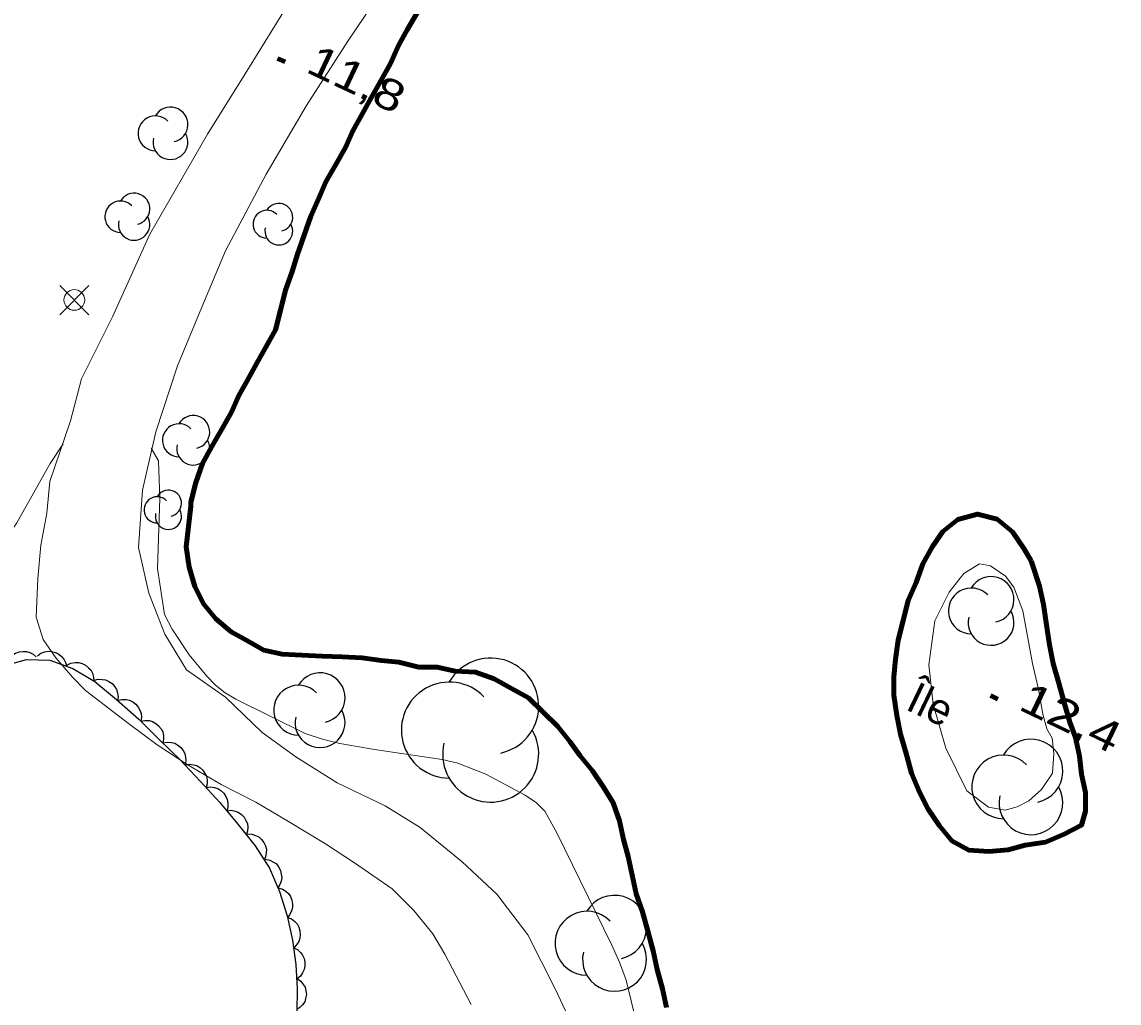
# Model space of a CAD drawing. Extents: x 355726 to 357533, y 5103782 to 5105258.
# Drawn here: x 356176.5 to 356229.5, y 5105042.4 to 5105089.8 of the extents above; entities that cross this region are included whole.
import ezdxf

# ---------------------------------------------------------------- set-up
doc = ezdxf.new("R2010")
doc.units = 0
doc.header["$LTSCALE"] = 0.6
for name, pattern in [('DASH_DOUBLE_DOT', [9.2, 5, -1.2, 0.3, -1.2, 0.3, -1.2]), ('DOT_DASHED', [7.7, 5, -1.2, 0.3, -1.2]), ('LONG_DASHED', [7.5, 6, -1.5])]:
    doc.linetypes.add(name, pattern=pattern)
for name, color, linetype, lineweight in [('19', 7, 'Continuous', 13), ('2', 7, 'LONG_DASHED', 13), ('3', 7, 'Continuous', 140), ('36', 7, 'Continuous', 13), ('4', 7, 'DASH_DOUBLE_DOT', 53), ('44', 7, 'Continuous', 25)]:
    doc.layers.add(name, color=color, linetype=linetype, lineweight=lineweight)
doc.layers.add('8', color=7, linetype='Continuous')

msp = doc.modelspace()

# ---------------------------------------------------------------- linework, layer by layer
at = {"layer": '19'}
for points in [[(356203.49, 5105040.41), (356202.22, 5105043.09), (356200.9, 5105045.7), (356199.41, 5105047.66), (356197.73, 5105049.22), (356195.7, 5105050.88), (356194.01, 5105051.93), (356191.69, 5105053.04), (356189.7, 5105054.3), (356188.06, 5105055.48), (356186.29, 5105057.18), (356184.41, 5105058.51), (356183.36, 5105060.24), (356182.59, 5105062.21), (356182.09, 5105064.43), (356182.28, 5105067.2), (356182.93, 5105070.01), (356183.98, 5105073.2), (356185.15, 5105076.04), (356186.3, 5105078.76), (356188.26, 5105082.47), (356190.2, 5105085.8), (356192.2, 5105088.9), (356194.22, 5105091.91)], [(356198.16, 5105042.32), (356196.89, 5105044.76), (356196.32, 5105045.74), (356195.39, 5105046.87), (356194.35, 5105047.92), (356192.53, 5105049.17), (356191.13, 5105050.09), (356189.34, 5105051.18), (356187.76, 5105052.11), (356186.09, 5105052.97), (356184.44, 5105053.93), (356182.99, 5105054.88), (356181.61, 5105055.91), (356179.53, 5105057.51), (356178.9, 5105058.16), (356178.09, 5105059.09), (356177.48, 5105059.98), (356177.14, 5105061.05), (356177.23, 5105062.93), (356177.37, 5105064.54), (356177.65, 5105066.08), (356177.81, 5105067.62), (356178.8, 5105070.54), (356179.33, 5105072.58), (356180.83, 5105075.57), (356182.63, 5105079.57), (356185.43, 5105084.4), (356187.25, 5105087.33), (356189.51, 5105091.01)]]:
    msp.add_lwpolyline(points, dxfattribs=at)
at = {"layer": '2', "linetype": 'Continuous'}
for points in [[(356167.83, 5105042.71), (356170, 5105049.92), (356170.19, 5105050.84), (356170.7, 5105052.83), (356172.2, 5105057.91), (356172.44, 5105058.83), (356172.7, 5105060.15), (356173.33, 5105061.38), (356174.21, 5105062.77), (356176.21, 5105065.62), (356177.82, 5105068.49), (356178.45, 5105069.43)], [(356182.7, 5105069.22), (356183.06, 5105068.62), (356183.12, 5105066.8), (356183, 5105063.4), (356183.35, 5105061.18), (356183.72, 5105060.48), (356184.53, 5105059.24), (356185.39, 5105058.2), (356185.81, 5105057.76), (356186.27, 5105057.4), (356186.79, 5105057.09), (356190.15, 5105055.43), (356190.98, 5105055.15), (356191.82, 5105054.95), (356193.49, 5105054.65), (356196.77, 5105054.17), (356197.52, 5105053.99), (356198.88, 5105053.47), (356200.77, 5105052.45), (356201.32, 5105052.08), (356201.72, 5105051.67), (356202.3, 5105050.62), (356204.95, 5105045.23), (356205.33, 5105044.38), (356205.65, 5105043.51), (356206.38, 5105040.51)]]:
    msp.add_lwpolyline(points, dxfattribs=at)
at = {"layer": '2'}
msp.add_lwpolyline([(356225.58, 5105057.57), (356225.29, 5105058.82), (356224.83, 5105061.36), (356224.39, 5105062.51), (356223.99, 5105063.03), (356223.27, 5105063.53), (356222.74, 5105063.63), (356221.98, 5105063.17), (356221.27, 5105062.27), (356220.58, 5105060.87), (356220.29, 5105058.75), (356220.5, 5105056.84), (356221.1, 5105054.72), (356222.12, 5105052.66), (356223.17, 5105051.87), (356223.97, 5105051.72), (356224.56, 5105051.88), (356225.12, 5105052.17), (356225.73, 5105052.72), (356226.27, 5105053.51), (356226.32, 5105054.47), (356226.24, 5105055.21), (356225.99, 5105055.65), (356225.79, 5105056.36)], close=True, dxfattribs=at)
at = {"layer": '3'}
for p, q in [((356188.81, 5105088.07), (356189.18, 5105087.9)), ((356223.26, 5105057.26), (356223.62, 5105057.09))]:
    msp.add_line(p, q, dxfattribs=at)
at = {"layer": '36'}
for p, q in [((356179.69, 5105075.68), (356178.28, 5105077.09)), ((356178.28, 5105075.68), (356179.69, 5105077.09))]:
    msp.add_line(p, q, dxfattribs=at)
msp.add_circle((356178.987, 5105076.391), 0.5, dxfattribs=at)
at = {"layer": '4', "linetype": 'Continuous', "lineweight": 90}
for points in [[(356195.55, 5105090.28), (356195.08, 5105089.45), (356194.66, 5105088.69), (356194.26, 5105087.82), (356193.8, 5105086.99), (356193.33, 5105086.16), (356192.91, 5105085.4), (356192.44, 5105084.57), (356192.09, 5105083.77), (356191.62, 5105082.94), (356191.15, 5105082.11), (356190.81, 5105081.31), (356190.41, 5105080.44), (356190.1, 5105079.53), (356189.78, 5105078.61), (356189.51, 5105077.77)], [(356189.51, 5105077.77), (356189.19, 5105076.86), (356188.95, 5105075.9), (356188.71, 5105074.94), (356188.24, 5105074.11), (356187.82, 5105073.36), (356187.35, 5105072.52), (356186.93, 5105071.77), (356186.58, 5105070.97), (356186.11, 5105070.14), (356185.64, 5105069.31), (356185.18, 5105068.48), (356184.86, 5105067.57), (356184.62, 5105066.61), (356184.61, 5105066.42), (356184.4, 5105064.45), (356184.54, 5105063.47), (356184.81, 5105062.53), (356185.23, 5105061.7), (356185.82, 5105060.97), (356186.56, 5105060.35), (356187.32, 5105059.93), (356188.15, 5105059.46), (356189.03, 5105059.27), (356189.99, 5105059.22), (356190.96, 5105059.17), (356191.93, 5105059.13), (356192.9, 5105059.08), (356193.82, 5105058.96), (356194.67, 5105058.88), (356195.63, 5105058.64), (356196.52, 5105058.64), (356197.4, 5105058.44), (356198.37, 5105058.4), (356199.28, 5105058.08), (356200.11, 5105057.61), (356200.94, 5105057.15), (356201.64, 5105056.46), (356202.35, 5105055.76), (356202.93, 5105055.04), (356203.44, 5105054.35), (356204.03, 5105053.63), (356204.57, 5105052.83), (356205.03, 5105052.07), (356205.34, 5105051.2), (356205.53, 5105050.3), (356205.76, 5105049.48), (356205.95, 5105048.58), (356206.14, 5105047.68), (356206.44, 5105046.81), (356206.71, 5105045.87), (356206.97, 5105044.92), (356207.16, 5105044.02), (356207.42, 5105043.08), (356207.61, 5105042.18)]]:
    msp.add_lwpolyline(points, dxfattribs=at)
msp.add_lwpolyline([(356225.23, 5105063.78), (356224.87, 5105064.38), (356224.33, 5105065.18), (356223.58, 5105065.8), (356222.63, 5105066.04), (356221.68, 5105065.77), (356220.96, 5105065.19), (356220.46, 5105064.47), (356219.99, 5105063.64), (356219.67, 5105062.73), (356219.28, 5105061.86), (356219.04, 5105060.9), (356218.8, 5105059.94), (356218.67, 5105059.02), (356218.59, 5105058.17), (356218.59, 5105057.28), (356218.74, 5105056.3), (356218.92, 5105055.4), (356219.19, 5105054.46), (356219.45, 5105053.51), (356219.83, 5105052.6), (356220.26, 5105051.77), (356220.8, 5105050.97), (356221.39, 5105050.24), (356222.22, 5105049.78), (356223.18, 5105049.73), (356224.12, 5105049.8), (356224.94, 5105050.03), (356225.92, 5105050.18), (356226.83, 5105050.56), (356227.67, 5105050.99), (356227.85, 5105051.68), (356227.86, 5105052.57), (356227.67, 5105053.47), (356227.56, 5105054.33), (356227.37, 5105055.23), (356227.1, 5105055.98), (356226.83, 5105056.92), (356226.57, 5105057.86), (356226.3, 5105058.81), (356226.12, 5105059.71), (356225.97, 5105060.68), (356225.82, 5105061.66), (356225.64, 5105062.56)], close=True, dxfattribs=at)
at = {"layer": '44', "linetype": 'DOT_DASHED'}
msp.add_lwpolyline([(356175.51, 5105058.68), (356176.67, 5105059.01), (356177.81, 5105058.97), (356178.92, 5105058.57), (356179.98, 5105057.95), (356181.03, 5105057.07), (356182.1, 5105056.12), (356183.11, 5105055.13), (356184.11, 5105054.15), (356185.07, 5105053.13), (356186.02, 5105052.09), (356186.89, 5105051.05), (356187.72, 5105049.99), (356188.42, 5105048.91), (356188.9, 5105047.79), (356189.27, 5105046.61), (356189.53, 5105045.44), (356189.69, 5105044.26), (356189.75, 5105043.08), (356189.74, 5105041.95)], dxfattribs=at)
at = {"layer": '44'}
for points in [[(356175.7, 5105058.73), (356175.76, 5105058.93), (356175.88, 5105059.1), (356175.99, 5105059.22), (356176.14, 5105059.31), (356176.32, 5105059.37), (356176.51, 5105059.4), (356176.67, 5105059.4), (356176.84, 5105059.34), (356177, 5105059.26), (356177.14, 5105059.14)], [(356177.2, 5105059.19), (356177.37, 5105059.31), (356177.56, 5105059.38), (356177.72, 5105059.41), (356177.89, 5105059.4), (356178.07, 5105059.35), (356178.24, 5105059.26), (356178.37, 5105059.16), (356178.48, 5105059.02), (356178.56, 5105058.86), (356178.61, 5105058.68)], [(356178.63, 5105058.74), (356178.82, 5105058.83), (356179.02, 5105058.86), (356179.19, 5105058.86), (356179.36, 5105058.81), (356179.52, 5105058.74), (356179.67, 5105058.61), (356179.78, 5105058.5), (356179.86, 5105058.34), (356179.92, 5105058.16), (356179.93, 5105057.98)], [(356179.93, 5105057.99), (356180.13, 5105058.05), (356180.34, 5105058.04), (356180.5, 5105058.02), (356180.66, 5105057.94), (356180.81, 5105057.84), (356180.94, 5105057.69), (356181.03, 5105057.56), (356181.08, 5105057.39), (356181.1, 5105057.2), (356181.08, 5105057.03)], [(356181.08, 5105057.02), (356181.28, 5105057.08), (356181.49, 5105057.07), (356181.65, 5105057.04), (356181.81, 5105056.96), (356181.96, 5105056.85), (356182.08, 5105056.7), (356182.16, 5105056.56), (356182.21, 5105056.39), (356182.23, 5105056.21), (356182.2, 5105056.03)], [(356182.2, 5105056.02), (356182.4, 5105056.06), (356182.61, 5105056.05), (356182.77, 5105056.01), (356182.92, 5105055.92), (356183.06, 5105055.8), (356183.18, 5105055.65), (356183.26, 5105055.51), (356183.29, 5105055.34), (356183.3, 5105055.15), (356183.27, 5105054.97)], [(356183.27, 5105054.97), (356183.48, 5105055.01), (356183.68, 5105055), (356183.84, 5105054.96), (356183.99, 5105054.87), (356184.13, 5105054.75), (356184.25, 5105054.6), (356184.33, 5105054.46), (356184.36, 5105054.29), (356184.37, 5105054.1), (356184.34, 5105053.92)], [(356184.33, 5105053.91), (356184.54, 5105053.95), (356184.74, 5105053.92), (356184.9, 5105053.88), (356185.05, 5105053.78), (356185.19, 5105053.66), (356185.29, 5105053.5), (356185.37, 5105053.36), (356185.4, 5105053.18), (356185.4, 5105053), (356185.36, 5105052.82)], [(356185.36, 5105052.82), (356185.56, 5105052.85), (356185.76, 5105052.82), (356185.92, 5105052.77), (356186.07, 5105052.68), (356186.21, 5105052.55), (356186.31, 5105052.39), (356186.38, 5105052.24), (356186.41, 5105052.07), (356186.41, 5105051.88), (356186.37, 5105051.71)], [(356186.35, 5105051.69), (356186.56, 5105051.72), (356186.76, 5105051.68), (356186.91, 5105051.62), (356187.06, 5105051.52), (356187.19, 5105051.39), (356187.28, 5105051.23), (356187.35, 5105051.08), (356187.37, 5105050.9), (356187.36, 5105050.72), (356187.31, 5105050.54)], [(356187.35, 5105050.57), (356187.56, 5105050.56), (356187.75, 5105050.5), (356187.9, 5105050.43), (356188.03, 5105050.31), (356188.14, 5105050.16), (356188.22, 5105049.99), (356188.27, 5105049.83), (356188.26, 5105049.66), (356188.23, 5105049.47), (356188.16, 5105049.31)], [(356188.23, 5105049.35), (356188.44, 5105049.31), (356188.62, 5105049.21), (356188.75, 5105049.12), (356188.86, 5105048.98), (356188.95, 5105048.81), (356188.99, 5105048.63), (356189.01, 5105048.47), (356188.98, 5105048.29), (356188.92, 5105048.12), (356188.82, 5105047.97)], [(356188.84, 5105047.97), (356189.04, 5105047.91), (356189.21, 5105047.8), (356189.34, 5105047.69), (356189.43, 5105047.54), (356189.5, 5105047.37), (356189.53, 5105047.18), (356189.53, 5105047.02), (356189.48, 5105046.85), (356189.4, 5105046.68), (356189.29, 5105046.54)], [(356189.29, 5105046.54), (356189.48, 5105046.46), (356189.64, 5105046.34), (356189.75, 5105046.22), (356189.83, 5105046.06), (356189.89, 5105045.89), (356189.9, 5105045.69), (356189.89, 5105045.53), (356189.83, 5105045.37), (356189.73, 5105045.21), (356189.61, 5105045.08)], [(356189.58, 5105045.07), (356189.77, 5105044.98), (356189.92, 5105044.84), (356190.02, 5105044.71), (356190.09, 5105044.55), (356190.13, 5105044.37), (356190.12, 5105044.18), (356190.1, 5105044.02), (356190.02, 5105043.86), (356189.92, 5105043.7), (356189.78, 5105043.58)], [(356189.75, 5105043.58), (356189.93, 5105043.46), (356190.05, 5105043.3), (356190.14, 5105043.16), (356190.18, 5105042.99), (356190.2, 5105042.81), (356190.16, 5105042.62), (356190.12, 5105042.46), (356190.02, 5105042.31), (356189.89, 5105042.18), (356189.74, 5105042.08)]]:
    msp.add_lwpolyline(points, dxfattribs=at)
for centre, radius, start, end in [((356183.633, 5105084.871), 0.844, 282.2692, 149.7263), ((356182.907, 5105084.449), 0.844, 44.1154, 269.804), ((356183.633, 5105084.027), 0.844, 166.9369, 29.6212), ((356181.877, 5105080.797), 0.759, 282.2692, 149.7263), ((356181.224, 5105080.417), 0.759, 44.1154, 269.804), ((356188.293, 5105080.055), 0.671, 44.1154, 269.804), ((356188.87, 5105080.391), 0.671, 282.2692, 149.7263), ((356181.877, 5105080.038), 0.759, 166.9369, 29.6212), ((356188.87, 5105079.72), 0.671, 166.9369, 29.6212), ((356184.733, 5105070.007), 0.798, 282.2692, 149.7263), ((356184.047, 5105069.608), 0.798, 44.1154, 269.804), ((356184.733, 5105069.209), 0.798, 166.9369, 29.6212), ((356183.534, 5105066.561), 0.633, 282.2692, 149.7263), ((356182.99, 5105066.244), 0.633, 44.1154, 269.804), ((356183.534, 5105065.928), 0.633, 166.9369, 29.6212), ((356223.293, 5105061.91), 1.109, 282.2692, 149.7263), ((356222.339, 5105061.355), 1.109, 44.1154, 269.804), ((356223.293, 5105060.801), 1.109, 166.9369, 29.6212), ((356199.11, 5105056.753), 2.321, 282.2692, 149.7263), ((356190.864, 5105057.16), 1.206, 282.2692, 149.7263), ((356197.113, 5105055.593), 2.321, 44.1154, 269.804), ((356189.827, 5105056.557), 1.206, 44.1154, 269.804), ((356190.864, 5105055.954), 1.206, 166.9369, 29.6212), ((356199.11, 5105054.432), 2.321, 166.9369, 29.6212), ((356225.223, 5105053.615), 1.539, 282.2692, 149.7263), ((356223.899, 5105052.845), 1.539, 44.1154, 269.804), ((356225.223, 5105052.075), 1.539, 166.9369, 29.6212), ((356205.096, 5105046.059), 1.547, 282.2692, 149.7263), ((356203.766, 5105045.285), 1.547, 44.1154, 269.804), ((356205.096, 5105044.512), 1.547, 166.9369, 29.6212)]:
    msp.add_arc(centre, radius, start, end, dxfattribs=at)

# ---------------------------------------------------------------- texts
at = {"layer": '3'}
for s, rotation, width, p in [('11,8   ', 334.72, 1.25, (356190.11, 5105087.44)), ('12,4   ', 334.423, 1.3, (356224.55, 5105056.62))]:
    msp.add_text(s, height=1.5, rotation=rotation, dxfattribs=dict(at, width=width)).set_placement(p)
at = {"layer": '8'}
msp.add_text('Île', height=1.5, rotation=334.42, dxfattribs=at).set_placement((356219.1, 5105056.62))

doc.saveas('drawing.dxf')
